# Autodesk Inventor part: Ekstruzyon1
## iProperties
Company: Autodesk, Inc.
Shininess: 64.0
Length Units: 11269
Angle Units: 11279
Time Units: 11290
Mass Units: 11283
Length Display Precision: 3
Angle Display Precision: 2
Compacted: True
Part Number: Ekstruzyon1
Document SubType Name: Modeling
Created: 2003-11
Catalog Web Link: www.autodesk.com
Vendor: Autodesk, Inc.
Designer: Administrator
Manufacturer: Standard
Standards Organization: Custom
Density: 1 g/cm^3
Density: 0.0
Volumn: 0.0
Area: 0.0
PropertySet Name: Model Information
Control State: 0
Master: False
Checked Out: False
Author: Administrator
